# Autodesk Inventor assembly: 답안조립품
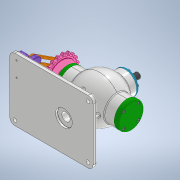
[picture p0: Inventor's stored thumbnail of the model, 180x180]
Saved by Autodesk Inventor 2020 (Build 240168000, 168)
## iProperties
Created: 2022-09
Part Number: 답안조립품
Document SubType Name: Assembly
Designer: 101-13
Author: 101-13
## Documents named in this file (20)
- C:\Users\101-13\Desktop\620906V1001\답안조립품.iam
- C:\Users\101-13\Desktop\620906V1001\본체.ipt
- C:\Users\101-13\Desktop\620906V1001\본체커버.ipt
- C:\Users\101-13\Desktop\620906V1001\베어링 6202.ipt
- C:\Users\101-13\Desktop\620906V1001\앞커버.ipt
- C:\Users\101-13\Desktop\620906V1001\뒤커버.ipt
- C:\Users\101-13\Desktop\620906V1001\축.ipt
- C:\Users\101-13\Desktop\620906V1001\오일실.ipt
- C:\Users\101-13\Desktop\620906V1001\와셔 8x17.ipt
- C:\Users\101-13\Desktop\620906V1001\너트 M8x1.ipt
- C:\Users\101-13\Desktop\620906V1001\키 3x3.ipt
- C:\Users\101-13\Desktop\620906V1001\스프로킷.ipt
- C:\Users\101-13\Desktop\620906V1001\힌지.ipt
- C:\Users\101-13\Desktop\620906V1001\커넥트 암.ipt
- C:\Users\101-13\Desktop\620906V1001\칼라.ipt
- C:\Users\101-13\Desktop\620906V1001\연결 핀.ipt
- C:\Users\101-13\Desktop\620906V1001\슬라이드.ipt
- C:\Users\101-13\Desktop\620906V1001\슬라이드 커버.ipt
- C:\Users\101-13\Desktop\620906V1001\볼트 M4x12.ipt
- C:\Users\101-13\Desktop\620906V1001\가변스프링.ipt
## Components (1 placed, 1 different names)
1. 가변스프링:1
